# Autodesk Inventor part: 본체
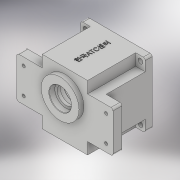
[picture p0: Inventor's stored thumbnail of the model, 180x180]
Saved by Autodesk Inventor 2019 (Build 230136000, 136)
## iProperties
Created: 2020-07
Part Number: 본체
Material: 일반
Document SubType Name: Modeling
Designer: Admin
Density: 1 g/cm^3
Appearance: 기본값
Author: Admin
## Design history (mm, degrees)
sketch "스케치1"
  geometry: L1 (-70, -30)-(70, -30); L2 (70, -30)-(70, 30); L3 (70, 30)-(-70, 30); L4 (-70, 30)-(-70, -30); L5 (-70, -30)-(70, 30); L6 (70, -30)-(-70, 30); 1 further point
  constraints: 12 end point, 2 midpoint, 2 parallel, 1 horizontal, 1 perpendicular
  dimensions: "d0" = 60 distance of L1.end L2.end; "d1" = 140 distance of L2.end L3.end
extrude "돌출1" new body sketch "스케치1" distance "d2" = 13; taper "d3" = 0 deg
sketch "스케치2"
  geometry: L1 (-47, -47)-(47, -47); L2 (47, -47)-(47, 47); L3 (47, 47)-(-47, 47); L4 (-47, 47)-(-47, -47); L5 (-47, -47)-(47, 47); L6 (47, -47)-(-47, 47); 1 further point
  constraints: 12 end point, 2 midpoint, 2 parallel, 1 horizontal, 1 perpendicular
  dimensions: "d4" = 94 distance of L2.end L3.end; "d5" = 94 distance of L1.end L2.end
extrude "돌출2" join sketch "스케치2" distance "d6" = 80; taper "d7" = 0 deg
sketch "스케치3"
  geometry: C1 r 27.5 at (0, 11); 1 further point
  constraints: 1 centre point
  dimensions: "d8" = 55 diameter of C1; "d9" = 11 distance of C1.centre point (0, 0)
extrude "돌출3" join sketch "스케치3" distance "d10" = 7; taper "d11" = 0 deg
sketch "스케치4"
  geometry: L1 (-33, -30)-(33, -30); L2 (33, -30)-(33, 30); L3 (33, 30)-(-33, 30); L4 (-33, 30)-(-33, -30); L5 (-33, -30)-(33, 30); L6 (33, -30)-(-33, 30); L7 (-47, 47)-(-47, 30) reference; L8 (-33, 30)-(-47, 30); L9 (-47, 30)-(-47, 47); L10 (-47, 47)-(-33, 47); L11 (-33, 47)-(-33, 30); L12 (47, 47)-(-47, 47) reference; L13 (33, 30)-(47, 30); L14 (47, 30)-(47, 47); L15 (47, 47)-(33, 47); L16 (33, 47)-(33, 30); L17 (-47, -47)-(47, -47) reference; L18 (33, -30)-(47, -30); L19 (47, -30)-(47, -47); L20 (47, -47)-(33, -47); L21 (33, -47)-(33, -30); L22 (-33, -30)-(-47, -30); L23 (-47, -30)-(-47, -47); L24 (-47, -47)-(-33, -47); L25 (-33, -47)-(-33, -30); 1 further point
  constraints: 44 end point, 10 parallel, 5 horizontal, 5 perpendicular, 2 midpoint
  dimensions: "d12" = 66 distance of L2.end L3.end; "d13" = 60 distance of L1.end L2.end
extrude "돌출4" cut sketch "스케치4" distance "d14" = 70; taper "d15" = 0 deg
sketch "스케치5"
  geometry: C1 r 27.5 at (0, 0) reference; C2 r 16 at (0, 0); 1 further point
  constraints: 1 centre point, 1 coincident
  dimensions: "d16" = 32 diameter of C2
extrude "돌출5" cut sketch "스케치5" distance "d17" = 8.3; taper "d18" = 0 deg
sketch "스케치6"
  geometry: L1 (-5, -1.3)-(27, -1.3) reference; L2 (-5, 7)-(27, 7) reference; L3 (38.5, 7)-(-16.5, 7) reference; L4 (11, 7)-(11, 6.2); L5 (11, 6.2)-(27, 6.2); L6 (27, 7)-(27, -1.3) reference; L7 (27, 6.2)-(27.462, 7); L8 (27.462, 7)-(11, 7); 1 further point
  constraints: 8 end point, 2 point on line, 1 collinear, 1 horizontal, 1 midpoint, 1 vertical
  dimensions: "d23" = 0.8 distance of L4.start L4.end; "d24" = 30 deg angle of L6 L7
revolve "회전1" sketch "스케치6" stored, may be unused: angle "d25" = 90 deg
sketch "스케치7"
  geometry: L1 (-60, -19)-(60, -19); L2 (60, -19)-(60, 19); L3 (60, 19)-(-60, 19); L4 (-60, 19)-(-60, -19); L5 (-60, -19)-(60, 19); L6 (60, -19)-(-60, 19); C1 r 2.25 at (-60, 19); C2 r 2.25 at (-60, -19); C3 r 2.25 at (60, -19); C4 r 2.25 at (60, 19); 1 further point
  constraints: 12 end point, 4 centre point, 4 coincident, 2 midpoint, 2 parallel, 1 horizontal, 1 perpendicular
  dimensions: "d26" = 38 distance of L1.end L2.end; "d27" = 120 distance of L1.start L1.end; "d28" = 4.5 diameter of C2; "d29" = 4.5 diameter of C1; "d30" = 4.5 diameter of C4; "d31" = 4.5 diameter of C3
extrude "돌출6" cut sketch "스케치7" stored distance "d32" = 0; taper "d33" = 0 deg
sketch "스케치8"
  geometry: C1 r 2.25 at (-60, 19) reference; C2 r 5 at (-60, 19); C3 r 2.25 at (-60, -19) reference; C4 r 5 at (-60, -19); C5 r 2.25 at (60, -19) reference; C6 r 5 at (60, -19); C7 r 2.25 at (60, 19) reference; C8 r 5 at (60, 19); 1 further point
  constraints: 4 centre point, 4 coincident
  dimensions: "d34" = 10 diameter of C2; "d35" = 10 diameter of C4; "d36" = 10 diameter of C6; "d37" = 10 diameter of C8
extrude "돌출7" cut sketch "스케치8" distance "d38" = 5; taper "d39" = 0 deg
fillet "모깎기1" dims "d40" = 3
fillet "모깎기2" dims "d41" = 3
sketch "스케치9"
  geometry: L1 (-40, -40)-(40, -40); L2 (40, -40)-(40, 40); L3 (40, 40)-(-40, 40); L4 (-40, 40)-(-40, -40); L5 (-40, -40)-(40, 40); L6 (40, -40)-(-40, 40); C1 r 3.5 at (-40, 40); C2 r 3.5 at (-40, -40); C3 r 3.5 at (40, -40); C4 r 3.5 at (40, 40); 1 further point
  constraints: 12 end point, 4 centre point, 4 coincident, 2 midpoint, 2 parallel, 1 horizontal, 1 perpendicular
  dimensions: "d42" = 80 distance of L2.end L3.end; "d43" = 80 distance of L1.end L2.end; "d44" = 7 diameter of C4; "d45" = 7 diameter of C3; "d46" = 7 diameter of C2; "d47" = 7 diameter of C1
extrude "돌출8" cut sketch "스케치9" stored distance "d48" = 5; taper "d49" = 0 deg
sketch "스케치10"
  geometry: C1 r 43 at (0, 0); 1 further point
  constraints: 1 centre point, 1 coincident
  dimensions: "d50" = 86 diameter of C1
extrude "돌출9" cut sketch "스케치10" distance "d51" = 9; taper "d52" = 0 deg
sketch "스케치11"
  geometry: A1 r 36 centre (0, 0) between (-36, 0) and (36, 0); A2 r 4 centre (-36, 0) between (-36.19, -3.995) and (-36.19, 3.995); A3 r 4 centre (36, 0) between (36.19, 3.995) and (36.19, -3.995); A4 r 3 centre (-36.333, -6.992) between (-35.772, -4.045) and (-39.279, -7.559); A5 r 3 centre (-36.333, 6.992) between (-39.279, 7.559) and (-35.772, 4.045); A6 r 3 centre (36.333, -6.992) between (39.279, -7.559) and (35.772, -4.045); A7 r 3 centre (36.333, 6.992) between (35.772, 4.045) and (39.279, 7.559); A8 r 40 centre (0, 0) between (-39.279, -7.559) and (39.279, -7.559); A9 r 40 centre (0, 0) between (39.279, 7.559) and (-39.279, 7.559); 1 further point
  constraints: 26 point on circle, 9 centre point, 4 tangent, 2 coincident
  dimensions: "d54" = 72 diameter of A1; "d55" = 8 diameter of A2; "d56" = 8 diameter of A3; "d57" = 6 diameter of A5; "d58" = 6 diameter of A4; "d59" = 6 diameter of A6; "d60" = 6 diameter of A7
extrude "돌출10" cut sketch "스케치11" distance "d61" = 62; taper "d62" = 0 deg
sketch "스케치12"
  geometry: A1 r 21 centre (0, 11) between (12.163, -6.119) and (-12.163, -6.119); A2 r 15 centre (0, -20) between (-11.584, -10.47) and (11.584, -10.47); A3 r 3 centre (-13.901, -8.565) between (-11.584, -10.47) and (-12.163, -6.119); A4 r 3 centre (13.901, -8.565) between (12.163, -6.119) and (11.584, -10.47); 1 further point
  constraints: 8 point on circle, 4 centre point, 4 tangent, 2 vertical alignment
  dimensions: "d63" = 42 diameter of A1; "d64" = 30 diameter of A2; "d65" = 11 distance of point (0, 0) A1.centre; "d66" = 20 distance of A2.centre point (0, 0); "d67" = 6 diameter of A3; "d68" = 6 diameter of A4
extrude "돌출11" join sketch "스케치12" distance "d69" = 7; taper "d70" = 0 deg
sketch "스케치13"
  geometry: C1 r 17.5 at (0, 11); 2 further points
  constraints: 1 centre point, 1 coincident
  dimensions: "d71" = 35 diameter of C1
extrude "돌출12" cut sketch "스케치13" distance "d72" = 10; taper "d73" = 0 deg
chamfer "모따기1" distance "d74" = 1; stored, may be unused: second distance "d75" = 2, angle "d76" = 45 deg
sketch "스케치14"
  geometry: C1 r 11 at (0, -20); A1 r 15 centre (0, -20) between (-11.584, -10.47) and (11.584, -10.47) reference; 1 further point
  constraints: 1 centre point, 1 coincident
  dimensions: "d77" = 22 diameter of C1
extrude "돌출13" cut sketch "스케치14" distance "d78" = 7; taper "d79" = 0 deg
sketch "스케치15"
  geometry: C1 r 27.5 at (0, 0) reference; C2 r 12.5 at (0, 0); 1 further point
  constraints: 1 centre point, 1 coincident
  dimensions: "d80" = 25 diameter of C2
extrude "돌출14" cut sketch "스케치15" stored distance "d81" = 0; taper "d82" = 0 deg
sketch "스케치16"
  geometry: C1 r 11 at (0, 0) reference; C2 r 9.5 at (0, 0); 1 further point
  constraints: 1 centre point, 1 coincident
  dimensions: "d83" = 19 diameter of C2
extrude "돌출15" cut sketch "스케치16" distance "d84" = 3; taper "d85" = 0 deg
chamfer "모따기2" distance "d86" = 1; stored, may be unused: second distance "d87" = 2, angle "d88" = 45 deg
sketch "스케치17"
  geometry: A1 r 4 centre (-36, 0) between (-36.19, -3.995) and (-36.19, 3.995) reference; A2 r 4 centre (36, 0) between (36.19, 3.995) and (36.19, -3.995) reference; 3 further points
  constraints: 2 coincident
hole "구멍1" sketch "스케치17" at (-36, 0), (36, 0) diameter "d89" = 3.242; stored, may be unused: countersink angle "d93" = 90 deg, drill point angle "d95" = 118 deg; dims "d90" = 7, "d91" = 4, "d92" = 2, "d94" = 9
sketch "스케치18"
  geometry: L1 (66, 0)-(0, 0) reference; L2 (-11, 80)-(77, 80) reference; 3 further points
  constraints: 1 midpoint, 1 vertical alignment, 1 other
  dimensions: "d96" = 40 distance from line of L2 point (33, 40)
feature "엠보싱1" sketch "스케치18" dims "d0" = 60, "d1" = 140, "d97" = 0.5, "d98" = 0
fillet "모깎기3" dims "d99" = 3
node "솔리드1"
node "투영된 루프1"
other parameters: "d19" = 0.5, "d20" = 2, "d21" = 0
